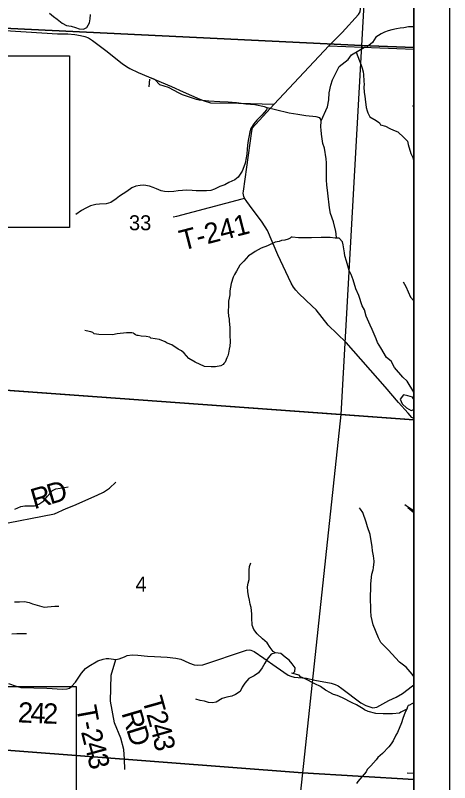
# Model space of a CAD drawing. Extents: x 0 to 34, y 0 to 22.
# Drawn here: x 7.784 to 9, y 17.231 to 19.378 of the extents above; entities that cross this region are included whole.
import ezdxf

# ---------------------------------------------------------------- set-up
doc = ezdxf.new("R2010")
doc.units = 0
for name, color, linetype in [('GM_X_Corporation', 7, 'Continuous'), ('GM_X_County_Road', 7, 'Continuous'), ('GM_X_Minor_Lake', 7, 'Continuous'), ('GM_X_Minor_River', 7, 'Continuous'), ('GM_X_Section_Text', 7, 'Continuous'), ('GM_X_Township_Road', 7, 'Continuous'), ('GM_X_Township_Road_Text', 7, 'Continuous'), ('SH_Data', 7, 'Continuous'), ('SH_Text', 7, 'Continuous')]:
    doc.layers.add(name, color=color, linetype=linetype)

msp = doc.modelspace()

# ---------------------------------------------------------------- linework, layer by layer
at = {"layer": 'GM_X_Corporation'}
for p, q in [((8.9, 18.0235), (8.9, 20.9)), ((8.9, 19.0688), (8.9, 19.9935)), ((8.9, 18.0245), (8.9, 19.0688)), ((8.9, 17.018), (8.9, 18.0245)), ((8.9, 14.1), (8.9, 18.0235))]:
    msp.add_line(p, q, dxfattribs=at)
for points in [[(6.4848, 18.4217), (8.9, 18.2459), (8.9, 20.9), (4.892, 20.9)], [(8.9, 14.1), (8.9, 18.2459), (6.4848, 18.4217)]]:
    msp.add_lwpolyline(points, dxfattribs=at)
for points in [[(7.8088, 20.2797), (8.8059, 20.2218), (8.7529, 19.294), (7.7331, 19.3433)], [(8.9, 19.2883), (8.9, 20.2153), (8.8059, 20.2218), (8.7529, 19.294)], [(7.7331, 19.3433), (8.7529, 19.294), (8.6957, 18.2606), (7.6778, 18.3345)], [(8.9, 18.2463), (8.9, 19.2883), (8.7529, 19.294), (8.6957, 18.2606)], [(7.6778, 18.3345), (8.6957, 18.2606), (8.5882, 17.2585), (7.5885, 17.3345)], [(8.9, 17.2392), (8.9, 18.2463), (8.6957, 18.2606), (8.5882, 17.2585)], [(7.5885, 17.3345), (8.5882, 17.2585), (8.4813, 16.2644), (7.4964, 16.3324)], [(8.9, 16.2326), (8.9, 17.2392), (8.5882, 17.2585), (8.4813, 16.2644)]]:
    msp.add_lwpolyline(points, close=True, dxfattribs=at)
at = {"layer": 'GM_X_County_Road'}
for p, q in [((8.509, 19.1298), (8.662, 19.2932)), ((8.662, 19.2932), (8.9, 19.2836))]:
    msp.add_line(p, q, dxfattribs=at)
msp.add_lwpolyline([(7.7112, 19.3388), (7.9024, 19.3267), (7.9317, 19.3261), (7.951, 19.324), (7.967, 19.3216), (7.9787, 19.3184), (7.9894, 19.3153), (8.0007, 19.3076), (8.0381, 19.2795), (8.083, 19.2429), (8.0955, 19.2352), (8.1053, 19.229), (8.128, 19.2182), (8.2212, 19.1793), (8.2545, 19.1638), (8.3007, 19.1432), (8.3128, 19.1389), (8.3303, 19.1334), (8.4094, 19.1323), (8.509, 19.1298)], dxfattribs=at)
at = {"layer": 'GM_X_Minor_Lake'}
for p, q in [((8.8744, 18.0092), (8.8846, 18.0019)), ((8.8846, 18.0019), (8.9, 17.992))]:
    msp.add_line(p, q, dxfattribs=at)
for points in [[(8.8958, 18.3091), (8.8829, 18.3129), (8.8704, 18.3164), (8.8612, 18.3035), (8.8669, 18.2909), (8.8794, 18.2799), (8.8919, 18.2723), (8.9, 18.2753)], [(8.9, 18.3039), (8.8988, 18.3045), (8.8958, 18.3091)]]:
    msp.add_lwpolyline(points, dxfattribs=at)
at = {"layer": 'GM_X_Minor_River'}
for p, q in [((8.9, 19.1243), (8.8956, 19.1241)), ((8.8695, 18.6323), (8.8771, 18.6189)), ((8.8771, 18.6189), (8.8903, 18.5896)), ((8.8903, 18.5896), (8.9, 18.5794)), ((7.9908, 18.4937), (7.979, 18.4957)), ((7.9961, 18.4925), (7.9908, 18.4937)), ((8.0018, 18.4902), (7.9961, 18.4925)), ((8.9, 17.2568), (8.8807, 17.2575))]:
    msp.add_line(p, q, dxfattribs=at)
for points in [[(7.8805, 19.384), (7.8911, 19.3749), (7.9018, 19.3673), (7.9154, 19.3566), (7.9279, 19.3501), (7.9405, 19.3474), (7.953, 19.3444), (7.9629, 19.3402), (7.9754, 19.339), (7.9849, 19.3436), (7.9918, 19.3572), (7.9937, 19.3683), (7.9948, 19.3804)], [(8.9, 19.3458), (8.885, 19.3458), (8.8717, 19.3435), (8.8611, 19.342), (8.8512, 19.3402), (8.8379, 19.3379), (8.828, 19.3349), (8.8178, 19.3307), (8.8079, 19.3266), (8.7938, 19.3167), (8.7839, 19.3023), (8.7694, 19.2903)], [(8.6403, 19.0825), (8.658, 19.1219), (8.6619, 19.1416), (8.6631, 19.1614), (8.667, 19.1826), (8.6724, 19.1974), (8.6908, 19.2349), (8.7156, 19.2541), (8.7256, 19.2677), (8.7614, 19.2888), (8.7694, 19.2903)], [(8.7381, 19.2751), (8.7525, 19.2387), (8.7555, 19.2299), (8.7581, 19.22), (8.7588, 19.2128), (8.7602, 19.1941), (8.7606, 19.185), (8.7602, 19.1782), (8.7609, 19.1622), (8.7627, 19.1519), (8.7631, 19.1432), (8.7664, 19.1204), (8.7694, 19.1108), (8.7709, 19.1048), (8.7769, 19.0941), (8.794, 19.0837), (8.8035, 19.0772), (8.8065, 19.0718), (8.8206, 19.0675), (8.8327, 19.061), (8.8426, 19.0564), (8.8551, 19.0521), (8.8722, 19.0364), (8.882, 19.0257), (8.8842, 19.0162), (8.891, 18.9918), (8.8974, 18.9807), (8.8996, 18.9701), (8.9, 18.969)], [(8.1604, 19.1994), (8.1577, 19.1782)], [(8.6829, 18.7545), (8.6827, 18.7667), (8.6812, 18.7732), (8.6749, 18.7999), (8.6662, 18.8235), (8.664, 18.8398), (8.6592, 18.8805), (8.6563, 18.9041), (8.6552, 18.9171), (8.6553, 18.9478), (8.655, 18.9649), (8.6543, 18.9763), (8.6495, 19.0064), (8.6446, 19.0194), (8.6417, 19.0452), (8.6402, 19.0574), (8.6399, 19.0654), (8.6403, 19.0825), (8.6388, 19.0882), (8.6366, 19.0909), (8.6267, 19.0936), (8.5978, 19.0968), (8.575, 19.1008), (8.5507, 19.104), (8.513, 19.1141), (8.4895, 19.1193), (8.4819, 19.122), (8.4545, 19.1275), (8.4291, 19.1299), (8.4036, 19.1332), (8.38, 19.1348), (8.3564, 19.1361), (8.3264, 19.1375), (8.2994, 19.1411), (8.2914, 19.1427), (8.272, 19.1489), (8.2527, 19.1555), (8.2432, 19.1605), (8.2128, 19.1759), (8.1893, 19.184), (8.1745, 19.1982), (8.1658, 19.2024), (8.1623, 19.2032)], [(8.4895, 19.1193), (8.4874, 19.1136), (8.4744, 19.0991), (8.46, 19.0843), (8.4524, 19.0741), (8.444, 19.0616), (8.4409, 19.0521), (8.4379, 19.0376), (8.4359, 19.0274), (8.4344, 19.0149), (8.4332, 19.0035), (8.4321, 18.9905), (8.4305, 18.9791), (8.4275, 18.9647), (8.4244, 18.9544), (8.4195, 18.9419), (8.408, 18.9252), (8.3985, 18.918), (8.3822, 18.9101), (8.3704, 18.904), (8.3564, 18.8987), (8.3419, 18.8919), (8.3316, 18.8881), (8.3195, 18.887), (8.3058, 18.887), (8.291, 18.8874), (8.2792, 18.8878), (8.264, 18.8886), (8.2519, 18.8882), (8.2405, 18.8867), (8.2276, 18.8849), (8.2124, 18.8845), (8.2018, 18.8853), (8.1923, 18.8868), (8.1794, 18.8922), (8.1699, 18.896), (8.16, 18.8998), (8.1444, 18.9029), (8.1342, 18.9021), (8.122, 18.8999), (8.1102, 18.8957), (8.0962, 18.8855), (8.0859, 18.879), (8.0764, 18.8718), (8.0669, 18.8642), (8.0517, 18.8544), (8.0391, 18.851), (8.0198, 18.8499), (8.0095, 18.8491), (7.9951, 18.8446), (7.9814, 18.8382), (7.9692, 18.8317), (7.9536, 18.8211)], [(8.9, 18.3236), (8.8814, 18.3545), (8.8689, 18.3656), (8.8458, 18.3928), (8.836, 18.4099), (8.8231, 18.4207), (8.8072, 18.4474), (8.7978, 18.4627), (8.794, 18.4726), (8.7827, 18.4993), (8.7774, 18.5114), (8.7665, 18.5362), (8.7617, 18.5537), (8.7556, 18.5648), (8.7459, 18.5945), (8.7376, 18.6124), (8.7297, 18.6376), (8.724, 18.6532), (8.7184, 18.6643), (8.7109, 18.6905), (8.7068, 18.7046), (8.7057, 18.713), (8.7016, 18.7362), (8.6997, 18.7438), (8.691, 18.7549), (8.688, 18.7549), (8.68, 18.7542), (8.6655, 18.7562), (8.6404, 18.7568), (8.613, 18.7551), (8.5952, 18.7552), (8.5765, 18.7557), (8.5594, 18.7577), (8.5564, 18.7577), (8.5533, 18.7543), (8.5476, 18.7517), (8.5388, 18.7491), (8.5293, 18.748), (8.5225, 18.7454), (8.5114, 18.7432), (8.4905, 18.7335), (8.4722, 18.7268), (8.4558, 18.717), (8.4459, 18.7102), (8.4367, 18.7054), (8.4241, 18.6902), (8.4123, 18.6789), (8.4031, 18.6623), (8.3981, 18.6528), (8.3939, 18.6456), (8.3885, 18.6274), (8.3849, 18.6069), (8.3845, 18.5955), (8.3826, 18.5864), (8.381, 18.578), (8.3806, 18.5617), (8.3802, 18.5541)], [(8.3802, 18.5541), (8.3805, 18.5488), (8.3812, 18.5359), (8.3827, 18.5275), (8.3831, 18.5218), (8.3845, 18.5043), (8.3848, 18.4971), (8.3851, 18.4784), (8.3855, 18.4693), (8.3855, 18.464), (8.3847, 18.4522), (8.3831, 18.4443), (8.3808, 18.4325), (8.3788, 18.4249), (8.3765, 18.4192), (8.3719, 18.4075), (8.3681, 18.4033), (8.3662, 18.4007), (8.3597, 18.3969), (8.3448, 18.3944), (8.3323, 18.3941), (8.314, 18.3957), (8.2878, 18.4073), (8.2696, 18.4181), (8.2571, 18.4322), (8.2492, 18.4395), (8.2405, 18.4441), (8.2226, 18.456), (8.209, 18.461), (8.2037, 18.4641), (8.1881, 18.4707), (8.1634, 18.475), (8.1607, 18.4777), (8.1508, 18.4793), (8.1364, 18.4802), (8.128, 18.4818), (8.125, 18.4822), (8.1212, 18.4837), (8.1174, 18.4868), (8.1147, 18.4883), (8.1102, 18.4891), (8.0957, 18.4892), (8.0695, 18.4863), (8.0562, 18.4841), (8.0185, 18.4852), (8.0052, 18.4872), (8.0018, 18.4902), (7.9961, 18.4925), (7.9908, 18.4937), (7.979, 18.4957)], [(7.7832, 17.996), (7.8003, 18.0032), (7.8114, 18.0055), (7.8258, 18.0055), (7.8379, 18.0058), (7.8505, 18.0104), (7.8645, 18.0191), (7.8744, 18.0327), (7.8885, 18.0483), (7.898, 18.0528), (7.9102, 18.0551), (7.9216, 18.057), (7.9322, 18.0585)], [(8.9, 17.5281), (8.8949, 17.5347), (8.8783, 17.5542), (8.8597, 17.568), (8.8275, 17.602), (8.8071, 17.6231), (8.8007, 17.6364), (8.786, 17.6726), (8.7804, 17.6962), (8.7797, 17.7118), (8.7783, 17.7525), (8.7792, 17.7745), (8.7796, 17.7867), (8.782, 17.814), (8.7859, 17.8265), (8.7867, 17.8322), (8.7882, 17.8421), (8.7886, 17.8467), (8.7883, 17.8505), (8.7864, 17.8653), (8.7838, 17.8798), (8.7827, 17.8908), (8.7776, 17.925), (8.7701, 17.9464), (8.7667, 17.9593), (8.7573, 17.9864), (8.7505, 17.9963), (8.7475, 18.0001)], [(8.5125, 17.5939), (8.5061, 17.598), (8.4981, 17.6091), (8.489, 17.6224), (8.4765, 17.6331), (8.4613, 17.6472), (8.4522, 17.6589), (8.447, 17.6719), (8.4462, 17.6924), (8.4459, 17.703), (8.4444, 17.7209), (8.4417, 17.7304), (8.4395, 17.7418), (8.4368, 17.754), (8.435, 17.7654), (8.4346, 17.7787), (8.4365, 17.7889), (8.4388, 17.7992), (8.4385, 17.8144), (8.4385, 17.8254), (8.4396, 17.8357), (8.4431, 17.8455)], [(7.7824, 17.7372), (7.7965, 17.7372), (7.8105, 17.738), (7.8231, 17.7349), (7.8329, 17.7315), (7.8519, 17.7253), (7.8648, 17.7219), (7.8743, 17.7223), (7.8846, 17.7234), (7.8948, 17.7245), (7.9058, 17.7249)], [(7.7743, 17.6472), (7.7883, 17.6479), (7.8028, 17.6479), (7.8157, 17.6483)], [(8.5614, 17.5358), (8.5671, 17.5421), (8.5675, 17.5516), (8.5592, 17.563), (8.5512, 17.5733), (8.5398, 17.582), (8.5273, 17.5919), (8.5125, 17.5939), (8.5007, 17.5901), (8.4889, 17.5764), (8.4829, 17.5647), (8.4752, 17.5517), (8.4653, 17.5385), (8.4528, 17.5294), (8.4383, 17.5222), (8.4265, 17.5089), (8.4193, 17.4975), (8.414, 17.4861), (8.4003, 17.477), (8.39, 17.4728), (8.3767, 17.4695), (8.363, 17.4661), (8.3463, 17.4562), (8.3361, 17.4543), (8.3254, 17.4555), (8.3137, 17.4585), (8.3015, 17.4605), (8.2894, 17.4643)], [(8.88, 17.4367), (8.8656, 17.4288), (8.8633, 17.4281), (8.8598, 17.4254), (8.8397, 17.4233), (8.8142, 17.4231), (8.7933, 17.4244), (8.7724, 17.4302), (8.7614, 17.4341), (8.7576, 17.4372), (8.7394, 17.4487), (8.7268, 17.4545), (8.6999, 17.468), (8.6855, 17.4742), (8.6752, 17.4777), (8.6627, 17.4838), (8.6559, 17.4877), (8.6528, 17.4896), (8.6384, 17.5), (8.6229, 17.5077), (8.5959, 17.5212), (8.5826, 17.5273), (8.5788, 17.5319), (8.5614, 17.5358), (8.5572, 17.5367)], [(8.9, 17.4542), (8.8976, 17.4533), (8.8946, 17.451), (8.8877, 17.4477), (8.8835, 17.4466), (8.8824, 17.4431), (8.88, 17.4367), (8.8758, 17.4276), (8.8689, 17.4106), (8.865, 17.3984), (8.8543, 17.3715), (8.8497, 17.3632), (8.8416, 17.3477), (8.8366, 17.3393), (8.8294, 17.3314), (8.8118, 17.3121), (8.7992, 17.3012), (8.7942, 17.2944), (8.7793, 17.2774), (8.7694, 17.2676), (8.7659, 17.2608), (8.7426, 17.2339), (8.7392, 17.2283)]]:
    msp.add_lwpolyline(points, dxfattribs=at)
at = {"layer": 'GM_X_Township_Road'}
for p, q in [((8.509, 19.1298), (8.662, 19.2932)), ((8.2266, 18.8141), (8.2366, 18.8158)), ((8.9, 17.9858), (8.8829, 18.0001)), ((7.7866, 17.5011), (7.8002, 17.4974)), ((7.9359, 17.4956), (7.9421, 17.5001))]:
    msp.add_line(p, q, dxfattribs=at)
for points in [[(8.662, 19.2932), (8.6992, 19.33), (8.7448, 19.38), (8.7499, 19.3875), (8.7519, 19.4118), (8.8097, 20.3858), (8.8436, 20.9)], [(8.8838, 18.2643), (8.8566, 18.2947), (8.8191, 18.3384), (8.7103, 18.4623), (8.6596, 18.5111), (8.626, 18.5541), (8.6151, 18.5638), (8.5783, 18.6), (8.5697, 18.6093), (8.5631, 18.6178), (8.5568, 18.6289), (8.5194, 18.7081), (8.4899, 18.7757), (8.4755, 18.7994), (8.4402, 18.8466), (8.4327, 18.8572), (8.4262, 18.8669), (8.4243, 18.8711), (8.423, 18.8755), (8.4224, 18.8803), (8.4226, 18.8864), (8.4462, 19.0542), (8.4483, 19.0633), (8.4568, 19.073), (8.509, 19.1298)], [(8.2366, 18.8158), (8.4191, 18.8643), (8.4262, 18.8669)], [(8.9, 18.2498), (8.8941, 18.2527), (8.8838, 18.2643)], [(7.6652, 17.9667), (7.6759, 17.9575), (7.6789, 17.9572), (7.7183, 17.9525), (7.7297, 17.9515), (7.8943, 17.983), (7.9266, 17.9983), (7.948, 18.0062), (8.0137, 18.0356), (8.0309, 18.0433), (8.0483, 18.0551), (8.0653, 18.0717)], [(7.7651, 17.5084), (7.7866, 17.5011), (7.8002, 17.4974), (7.8728, 17.4947), (7.9161, 17.4926), (7.9291, 17.4931), (7.9359, 17.4956), (7.9421, 17.5001), (7.953, 17.512), (7.9699, 17.5368), (7.9812, 17.5502), (7.9901, 17.5569), (8.0151, 17.5716), (8.0305, 17.5762), (8.0385, 17.5779), (8.0461, 17.5778), (8.0658, 17.5751), (8.075, 17.5768), (8.0899, 17.5829), (8.0976, 17.5866), (8.1117, 17.5889), (8.1269, 17.5879), (8.1542, 17.585), (8.1736, 17.5838), (8.2093, 17.5819), (8.234, 17.5795), (8.248, 17.5765), (8.2581, 17.5718), (8.2721, 17.565), (8.2849, 17.5609), (8.2944, 17.5592), (8.3096, 17.5608), (8.4314, 17.6012), (8.4386, 17.6022), (8.4436, 17.6017), (8.453, 17.5973), (8.4797, 17.5789)], [(8.0911, 17.2672), (8.0899, 17.2965), (8.0885, 17.3236), (8.0797, 17.3549), (8.0624, 17.3983), (8.0508, 17.459), (8.0531, 17.5316), (8.0658, 17.5751)], [(8.4797, 17.5789), (8.5144, 17.5549), (8.5485, 17.5314), (8.5557, 17.529), (8.5652, 17.5261), (8.5993, 17.5231), (8.6224, 17.5177), (8.6682, 17.5087), (8.6799, 17.505), (8.6882, 17.5014), (8.6979, 17.494), (8.7511, 17.4545), (8.7654, 17.4466), (8.7737, 17.4437), (8.785, 17.4404), (8.7961, 17.4417), (8.8296, 17.4608), (8.8503, 17.4699), (8.868, 17.4798), (8.8962, 17.5016), (8.9, 17.5047)]]:
    msp.add_lwpolyline(points, dxfattribs=at)
at = {"layer": 'SH_Data'}
for p, q in [((9, 21), (9, 14)), ((8.9, 20.9), (8.9, 14.1)), ((6.0621, 17.4995), (7.9543, 17.4995)), ((7.9543, 17.4995), (7.9543, 17.0126))]:
    msp.add_line(p, q, dxfattribs=at)
at = {"layer": 'SH_Text'}
msp.add_lwpolyline([(7.4168, 19.265), (7.9364, 19.265), (7.9364, 18.784), (6.6994, 18.784)], dxfattribs=at)

# ---------------------------------------------------------------- texts
at = {"layer": 'GM_X_Section_Text'}
for s, height, p in [('33', 0.04186, (8.1026, 18.7767)), ('4', 0.0419, (8.1209, 17.7654))]:
    msp.add_text(s, height=height, rotation=0, dxfattribs=at).set_placement(p)
at = {"layer": 'GM_X_Township_Road_Text'}
for s, height, rotation, p in [('T-241', 0.05682, 14.4438, (8.2522, 18.7195)), ('R', 0.0568, 16.1807, (7.8372, 17.9956)), ('D', 0.0568, 16.8398, (7.8827, 18.0088)), ('T', 0.0568, 285.8347, (8.1391, 17.4637)), ('2', 0.0568, 357.4557, (7.7907, 17.3996)), ('4', 0.0568, 357.693, (7.8259, 17.398)), ('2', 0.0568, 357.8855, (7.8611, 17.3966)), ('T', 0.0568, 280.3156, (7.9547, 17.4418)), ('R', 0.0568, 286.4376, (8.0811, 17.4255)), ('2', 0.0568, 285.8339, (8.1507, 17.4228)), ('-', 0.0568, 281.8589, (7.9626, 17.3984)), ('2', 0.0568, 284.0024, (7.9679, 17.3733)), ('D', 0.0568, 287.4731, (8.0946, 17.3797)), ('4', 0.0568, 285.8362, (8.1603, 17.3891)), ('3', 0.0568, 281.1017, (8.1695, 17.3566)), ('4', 0.0568, 285.1112, (7.9767, 17.3382)), ('3', 0.0568, 282.7501, (7.9857, 17.305))]:
    msp.add_text(s, height=height, rotation=rotation, dxfattribs=at).set_placement(p)

doc.saveas('drawing.dxf')
